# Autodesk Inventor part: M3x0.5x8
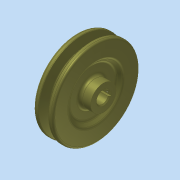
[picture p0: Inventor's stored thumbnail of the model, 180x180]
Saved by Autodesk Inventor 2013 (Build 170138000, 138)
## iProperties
Company: 한국ATC센터
Created: 2009-02
Part Number: M3x0.5x8
Document SubType Name: Modeling
Designer: KYOUNG IL JANG
Density: 7.25 g/cm^3
Mass: 594.644 g
Surface Area: 210.328 cm^2
Volume: 82.0198 cm^3
Material: 주철
Vendor: CBT Solutions
Author: KYOUNG IL JANG
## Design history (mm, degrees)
sketch "스케치1"
  geometry: L1 (-13, 0)-(13, 0); L2 (-13, 0)-(-13, 12.5); L3 (-13, 12.5)-(-9, 12.5); L4 (-9, 12.5)-(-9, 23); L5 (-9, 23)-(-13, 27); L6 (-13, 27)-(-13, 42.7); L7 (-13, 42.7)-(-8.325, 42.7); L8 (-8.325, 42.7)-(-5.574, 33.7); L9 (-5.574, 33.7)-(-1.426, 33.7); L10 (-1.426, 33.7)-(1.325, 42.7); L11 (1.325, 42.7)-(6, 42.7); L12 (6, 42.7)-(6, 27); L13 (6, 27)-(2, 23); L14 (2, 23)-(2, 12.5); L15 (2, 12.5)-(13, 12.5); L16 (13, 12.5)-(13, 0); L17 (-7.5, 40)-(0.5, 40); 2 further points
  constraints: 34 end point, 6 parallel, 5 collinear, 5 equal length, 4 perpendicular, 2 point on line, 1 coincident, 1 horizontal, 1 midpoint
  dimensions: "d0" = 26 distance of L1.start L1.end; "d1" = 2.7 distance between parallel lines of L7 L17; "d2" = 6.3 distance between parallel lines of L9 L17; "d3" = 8 distance of L17.start L17.end; "d4" = 34 deg angle of L10 L8; "d5" = 19 distance between parallel lines of L12 L6; "d7" = 25 diameter of L15 L1; "d8" = 46 diameter of L13.end L1; "d9" = 54 diameter of L12.end L1; "d10" = 4 distance between parallel lines of L2 L4; "d11" = 80 diameter of L17 L1
revolve "회전1" sketch "스케치1" stored, may be unused: angle "d12" = 90 deg
sketch "스케치2"
  geometry: L1 (-2, 5.657)-(-2, 7.8); L2 (-2, 7.8)-(2, 7.8); L3 (2, 7.8)-(2, 5.657); A1 r 6 centre (0, 0) between (-2, 5.657) and (2, 5.657); 1 further point
  constraints: 6 end point, 2 parallel, 2 point on circle, 1 centre point, 1 coincident, 1 perpendicular, 1 vertical
  dimensions: "d13" = 12 diameter of A1; "d14" = 13.8 dimension on A1 L2; "d15" = 4 distance of L1.end L2.end
extrude "돌출1" cut sketch "스케치2" stored distance "d16" = 10; taper "d17" = 0 deg
node "작업 평면1"
sketch "스케치3"
  geometry: L1 (-5.5, 12.5)-(-5.5, -12.5) reference; 3 further points
  constraints: 1 horizontal alignment, 1 midpoint
  dimensions: "d18" = 4 distance from line of point (-1.5, 0) L1
hole "구멍1" sketch "스케치3" at (-1.5, 0) diameter "d19" = 2.459; stored, may be unused: countersink angle "d23" = 90 deg, drill point angle "d25" = 118 deg; dims "d20" = 6, "d21" = 4, "d22" = 2, "d24" = 8
fillet "모깎기1" dims "d26" = 2, "d27" = 0.5, "d28" = 1, "d29" = 3
chamfer "모따기1" distance "d30" = 1; stored, may be unused: second distance "d31" = 2, angle "d32" = 45 deg
node "솔리드1"
